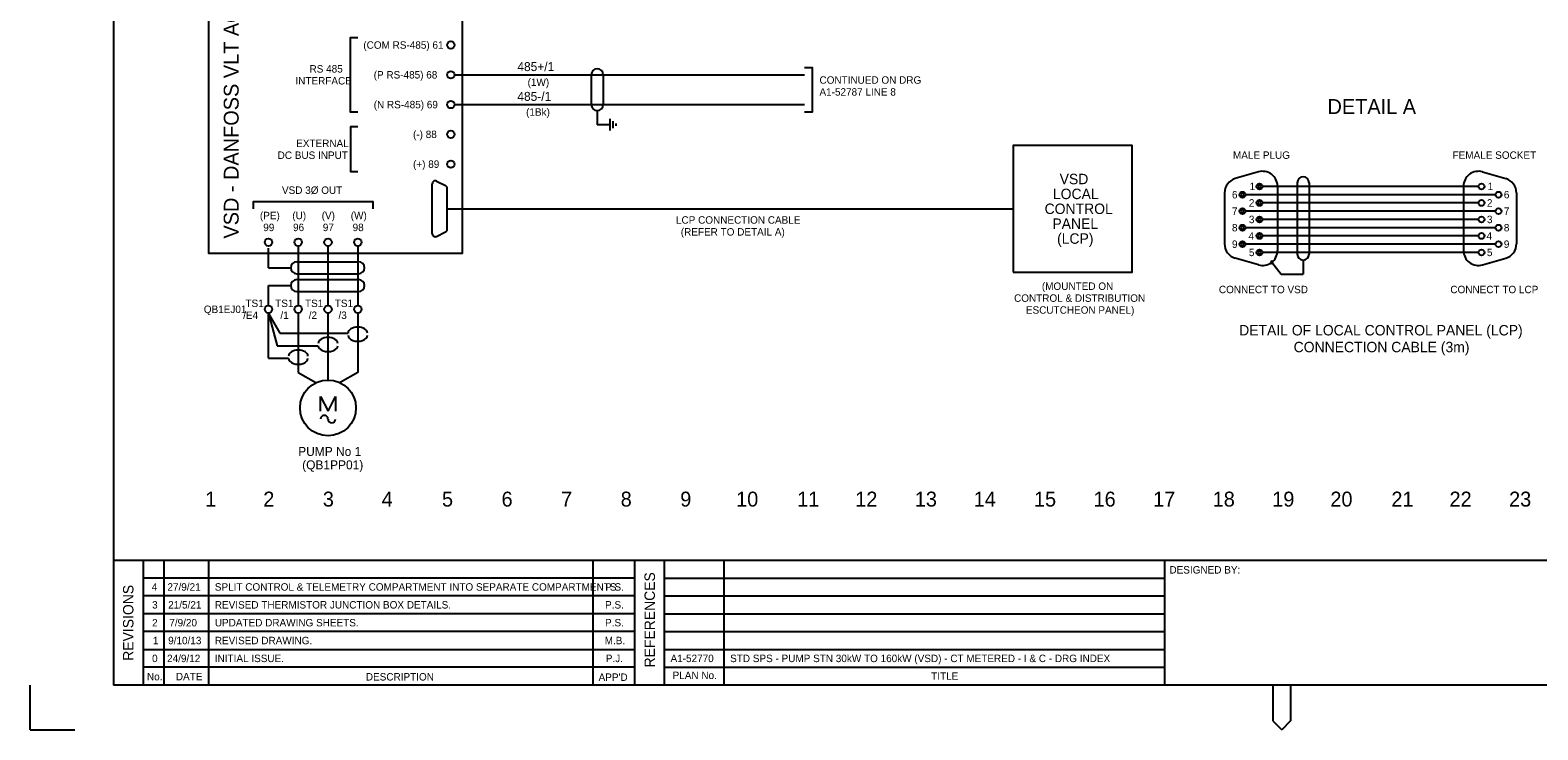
# Model space of a CAD drawing. Extents: x 0 to 841, y 0 to 594.
# Drawn here: x 0 to 506, y 0 to 235 of the extents above; entities that cross this region are included whole.
import ezdxf

# ---------------------------------------------------------------- set-up
doc = ezdxf.new("R2010")
doc.units = 0
for name, color, linetype in [('A1BORDER', 7, 'Continuous'), ('BASE', 7, 'Continuous'), ('Level 1', 7, 'Continuous'), ('Level 10', 7, 'Continuous'), ('Level 4', 7, 'Continuous'), ('Level 5', 7, 'Continuous'), ('Level 6', 7, 'Continuous'), ('Screen', 7, 'Continuous')]:
    doc.layers.add(name, color=color, linetype=linetype)

msp = doc.modelspace()

# ---------------------------------------------------------------- linework, layer by layer
at = {"layer": 'A1BORDER'}
for p, q in [((28, 581), (28, 15)), ((28, 57), (829, 57)), ((38, 15), (38, 57)), ((45, 15), (45, 57)), ((60, 15), (60, 57)), ((189, 15), (189, 57)), ((203, 15), (203, 57)), ((213, 15), (213, 57)), ((233, 15), (233, 57)), ((381, 15), (381, 57)), ((203, 51), (38, 51)), ((213, 51), (381, 51)), ((203, 45), (38, 45)), ((213, 45), (381, 45)), ((203, 39), (38, 39)), ((213, 39), (381, 39)), ((203, 33), (38, 33)), ((213, 33), (381, 33)), ((38, 27), (203, 27)), ((213, 27), (381, 27)), ((203, 21), (38, 21)), ((213, 21), (381, 21)), ((0, 0), (0, 15)), ((829, 15), (28, 15)), ((417.19, 15), (417.19, 3)), ((423.19, 15), (423.19, 3)), ((0, 0), (15, 0)), ((417.19, 3), (420.19, 0)), ((423.19, 3), (420.19, 0))]:
    msp.add_line(p, q, dxfattribs=at)
at = {"layer": 'BASE'}
for p, q in [((188.37, 220), (188.37, 210)), ((192.37, 220), (192.37, 210)), ((190.37, 208), (190.37, 203.25)), ((194.74, 203.25), (190.37, 203.25)), ((412.38, 187.39), (404.58, 185.12)), ((487.62, 187.39), (495.42, 185.12)), ((486.28, 182.5), (413.72, 182.5)), ((418.78, 182.59), (418.78, 160.97)), ((425.39, 183.76), (425.39, 159.8)), ((429.39, 183.76), (429.39, 159.8)), ((481.22, 182.59), (481.22, 160.97)), ((400.98, 180.32), (400.98, 163.24)), ((491.96, 179.73), (408.04, 179.73)), ((499.02, 180.32), (499.02, 163.24)), ((491.96, 174.19), (408.04, 174.19)), ((486.28, 176.96), (413.72, 176.96)), ((491.96, 168.65), (408.04, 168.65)), ((486.28, 171.42), (413.72, 171.42)), ((491.96, 163.11), (408.04, 163.11)), ((486.28, 165.88), (413.72, 165.88)), ((412.38, 156.17), (404.58, 158.44)), ((486.28, 160.34), (413.72, 160.34)), ((416.87, 157.04), (420.02, 153.05)), ((427.39, 157.8), (427.39, 153.05)), ((487.62, 156.17), (495.42, 158.44)), ((420.02, 153.05), (427.39, 153.05))]:
    msp.add_line(p, q, dxfattribs=at)
for centre in [(412.72, 182.5), (487.28, 182.5), (407.04, 179.73), (412.72, 176.96), (487.28, 176.96), (492.96, 179.73), (407.04, 174.19), (412.72, 171.42), (487.28, 171.42), (492.96, 174.19), (407.04, 168.65), (492.96, 168.65), (407.04, 163.11), (412.72, 165.88), (487.28, 165.88), (492.96, 163.11), (412.72, 160.34), (487.28, 160.34)]:
    msp.add_circle(centre, 1, dxfattribs=at)
for centre, radius, start, end in [((190.37, 220), 2, 0, 180), ((190.37, 210), 2, 180, 0), ((413.78, 182.59), 5, 0, 106.2177), ((486.22, 182.59), 5, 73.7823, 180), ((405.98, 180.32), 5, 106.2177, 180), ((412.72, 182.5), 0.5, 0, 180), ((412.72, 182.5), 0.5, 180, 0), ((427.39, 183.76), 2, 0, 180), ((494.02, 180.32), 5, 0, 73.7823), ((407.04, 179.73), 0.5, 0, 180), ((407.04, 179.73), 0.5, 180, 0), ((412.72, 176.96), 0.5, 0, 180), ((407.04, 174.19), 0.5, 0, 180), ((407.04, 174.19), 0.5, 180, 0), ((412.72, 176.96), 0.5, 180, 0), ((407.04, 168.65), 0.5, 0, 180), ((407.04, 168.65), 0.5, 180, 0), ((412.72, 171.42), 0.5, 0, 180), ((412.72, 171.42), 0.5, 180, 0), ((405.98, 163.24), 5, 180, 253.7823), ((407.04, 163.11), 0.5, 0, 180), ((407.04, 163.11), 0.5, 180, 0), ((412.72, 165.88), 0.5, 0, 180), ((412.72, 165.88), 0.5, 180, 0), ((494.02, 163.24), 5, 286.2177, 0), ((412.72, 160.34), 0.5, 0, 180), ((412.72, 160.34), 0.5, 180, 0), ((413.78, 160.97), 5, 253.7823, 0), ((416.87, 157.04), 0.375, 0, 180), ((416.87, 157.04), 0.375, 180, 0), ((427.39, 159.8), 2, 180, 0), ((486.22, 160.97), 5, 180, 286.2177)]:
    msp.add_arc(centre, radius, start, end, dxfattribs=at)
at = {"layer": 'Level 1'}
for p, q in [((135, 166.62), (135, 183.38)), ((136.45, 184.28), (139.45, 182.78)), ((140, 168.12), (140, 181.88)), ((140, 175), (330, 175)), ((136.45, 165.72), (139.45, 167.22)), ((90, 162.5), (90, 142.5)), ((100, 142.5), (100, 162.5)), ((110, 162.5), (110, 142.5)), ((90, 140), (90, 120)), ((100, 117.5), (100, 140)), ((110, 140), (110, 120))]:
    msp.add_line(p, q, dxfattribs=at)
for points in [[(60, 480), (145, 480), (145, 160), (60, 160)], [(330, 153.75), (370, 153.75), (370, 196.25), (330, 196.25)]]:
    msp.add_lwpolyline(points, close=True, dxfattribs=at)
for points in [[(110, 207.5), (107.5, 207.5), (107.5, 232.5), (110, 232.5)], [(260, 222.5), (262.5, 222.5), (262.5, 207.5), (260, 207.5)], [(110, 202.5), (107.5, 202.5), (107.5, 187.5), (110, 187.5)], [(75, 175), (75, 177.5), (115, 177.5), (115, 175)]]:
    msp.add_lwpolyline(points, dxfattribs=at)
for centre, start, end in [((136, 183.38), 63.4349, 180), ((139, 181.88), 0, 63.4349), ((139, 168.12), 296.5651, 360), ((136, 166.62), 180, 296.5651)]:
    msp.add_arc(centre, 1, start, end, dxfattribs=at)
at = {"layer": 'Level 10'}
for p, q in [((194.74, 201.25), (194.74, 205.25)), ((195.74, 202.05), (195.74, 204.45)), ((196.74, 202.85), (196.74, 203.65))]:
    msp.add_line(p, q, dxfattribs=at)
at = {"layer": 'Level 4'}
for p, q in [((97.49, 112), (100, 107)), ((97.49, 107), (97.49, 112)), ((100, 107), (102.51, 112)), ((102.51, 112), (102.51, 107))]:
    msp.add_line(p, q, dxfattribs=at)
for centre, radius in [((80, 163.75), 1.25), ((90, 163.75), 1.25), ((100, 163.75), 1.25), ((110, 163.75), 1.25), ((80, 141.25), 1.25), ((90, 141.25), 1.25), ((100, 141.25), 1.25), ((110, 141.25), 1.25), ((100, 108.12), 9.38)]:
    msp.add_circle(centre, radius, dxfattribs=at)
for centre, start, end in [((98.75, 104.38), 0, 180), ((101.25, 104.38), 180, 360)]:
    msp.add_arc(centre, 1.24, start, end, dxfattribs=at)
at = {"layer": 'Level 5'}
for p, q in [((90, 120), (95.89, 116.61)), ((110, 120), (104.11, 116.61))]:
    msp.add_line(p, q, dxfattribs=at)
for centre in [(141.25, 230), (141.25, 220), (141.25, 210), (141.25, 200), (141.25, 190)]:
    msp.add_circle(centre, 1.25, dxfattribs=at)
at = {"layer": 'Level 6'}
for p, q in [((142.5, 220), (260, 220)), ((142.5, 210), (260, 210))]:
    msp.add_line(p, q, dxfattribs=at)
at = {"layer": 'Screen'}
for p, q in [((80, 155.21), (80, 161.82)), ((89.52, 157.21), (110.27, 157.21)), ((80, 155.21), (87.52, 155.21)), ((89.52, 153.21), (110.27, 153.21)), ((80, 149.21), (87.52, 149.21)), ((80, 142.37), (80, 149.21)), ((89.52, 151.21), (110.27, 151.21)), ((89.52, 147.21), (110.27, 147.21)), ((80, 139.87), (82.9, 129.03)), ((80, 124.78), (80, 139.87)), ((80, 139.87), (83.8, 133.28)), ((83.8, 133.28), (106.75, 133.28)), ((82.9, 129.03), (96.75, 129.03)), ((80, 124.78), (86.75, 124.78))]:
    msp.add_line(p, q, dxfattribs=at)
for centre, start, end in [((89.52, 155.21), 90, 270), ((110.27, 155.21), 270, 90), ((89.52, 149.21), 90, 270), ((110.27, 149.21), 270, 90)]:
    msp.add_arc(centre, 2, start, end, dxfattribs=at)
for centre, start_param, end_param in [((100, 129.78), 3.141593, 6.283185), ((110, 133.28), 3.141593, 6.283185), ((110, 132.53), 0, 3.141593), ((90, 125.53), 3.141593, 6.283185), ((100, 129.03), 0, 3.141593), ((90, 124.78), 0, 3.141593)]:
    msp.add_ellipse(centre, major_axis=(-3.25, 0), ratio=0.615385, start_param=start_param, end_param=end_param, dxfattribs=at)

# ---------------------------------------------------------------- texts
at = {"layer": 'A1BORDER'}
for s, p in [('REFERENCES', (209.76, 20.96)), ('REVISIONS', (34.68, 23.2))]:
    msp.add_text(s, height=3.5, rotation=90, dxfattribs=at).set_placement(p)
for s, p in [('DESIGNED BY:', (382.5, 52.5)), ('No.', (39.21, 16.65)), ('DATE', (48.92, 16.65)), ('DESCRIPTION', (112.71, 16.57)), ("APP'D", (190.85, 16.44)), ('PLAN No.', (215.69, 17.06)), ('TITLE', (302.5, 16.81))]:
    msp.add_text(s, height=2.5, dxfattribs=at).set_placement(p)
at = {"layer": 'BASE'}
for s, height, p in [('DETAIL A', 5, (435.56, 206.84)), ('MALE PLUG', 2.5, (403.83, 191.78)), ('FEMALE SOCKET', 2.5, (477.56, 191.78)), ('1', 2.5, (409.42, 181.26)), ('1', 2.5, (489.34, 181.26)), ('6', 2.5, (403.49, 178.49)), ('2', 2.5, (409.17, 175.72)), ('2', 2.5, (489.09, 175.72)), ('6', 2.5, (494.77, 178.49)), ('7', 2.5, (403.49, 172.95)), ('3', 2.5, (409.17, 170.18)), ('3', 2.5, (489.09, 170.18)), ('7', 2.5, (494.77, 172.95)), ('8', 2.5, (403.49, 167.41)), ('4', 2.5, (409.05, 164.64)), ('4', 2.5, (488.96, 164.64)), ('8', 2.5, (494.77, 167.41)), ('9', 2.5, (403.49, 161.87)), ('9', 2.5, (494.77, 161.87)), ('5', 2.5, (409.17, 159.1)), ('5', 2.5, (489.09, 159.1)), ('CONNECT TO VSD', 2.5, (399.1, 146.65)), ('CONNECT TO LCP', 2.5, (476.81, 146.65)), ('DETAIL OF LOCAL CONTROL PANEL (LCP)', 3.5, (405.9, 132.47)), ('CONNECTION CABLE (3m)', 3.5, (424.2, 126.82))]:
    msp.add_text(s, height=height, dxfattribs=at).set_placement(p)
at = {"layer": 'Level 1'}
msp.add_text('VSD - DANFOSS VLT AQUA FC 202', height=5, rotation=90, dxfattribs=at).set_placement((70, 165))
for s, height, p in [('(COM RS-485) 61', 2.5, (111.85, 228.75)), ('RS 485', 2.5, (93.79, 220.75)), ('INTERFACE', 2.5, (89.06, 216.75)), ('(P RS-485) 68', 2.5, (115.34, 218.75)), ('CONTINUED ON DRG', 2.5, (265, 217)), ('A1-52787 LINE 8', 2.5, (265, 213)), ('(N RS-485) 69', 2.5, (115.34, 208.75)), ('EXTERNAL', 2.5, (89.31, 195.75)), ('(-) 88', 2.5, (128.54, 198.75)), ('DC BUS INPUT', 2.5, (83.09, 191.75)), ('(+) 89', 2.5, (128.54, 188.75)), ('VSD 3Ø OUT', 2.5, (84.54, 180)), ('VSD', 3.5, (345.64, 183.25)), ('LOCAL', 3.5, (343.38, 178.25)), ('(PE)', 2.5, (77.14, 171.5)), ('(U)', 2.5, (88.01, 171.5)), ('(V)', 2.5, (97.88, 171.5)), ('(W)', 2.5, (107.64, 171.5)), ('LCP CONNECTION CABLE', 2.5, (216.82, 170)), ('CONTROL', 3.5, (340.59, 173.25)), ('99', 2.5, (78.26, 167.5)), ('96', 2.5, (88.26, 167.5)), ('97', 2.5, (98.26, 167.5)), ('98', 2.5, (108.26, 167.5)), ('(REFER TO DETAIL A)', 2.5, (218.44, 166)), ('PANEL', 3.5, (343.2, 168.25)), ('(LCP)', 3.5, (344.77, 163.25)), ('(MOUNTED ON', 2.5, (339.67, 147.76)), ('CONTROL & DISTRIBUTION', 2.5, (330.33, 143.76)), ('ESCUTCHEON PANEL)', 2.5, (334.31, 139.76)), ('PUMP No 1', 3, (89.99, 92)), ('(QB1PP01)', 3, (91.33, 87.5)), ('1', 5, (58.76, 75)), ('2', 5, (78.26, 75)), ('3', 5, (98.26, 75)), ('4', 5, (118.01, 75)), ('5', 5, (138.26, 75)), ('6', 5, (158.26, 75)), ('7', 5, (178.26, 75)), ('8', 5, (198.26, 75)), ('9', 5, (218.26, 75)), ('10', 5, (237.01, 75)), ('11', 5, (257.51, 75)), ('12', 5, (277.01, 75)), ('13', 5, (297.01, 75)), ('14', 5, (316.77, 75)), ('15', 5, (337.01, 75)), ('16', 5, (357.01, 75)), ('17', 5, (377.01, 75)), ('18', 5, (397.01, 75)), ('19', 5, (417.01, 75)), ('20', 5, (436.52, 75)), ('21', 5, (457.01, 75)), ('22', 5, (476.52, 75)), ('23', 5, (496.52, 75)), ('4', 2.5, (40.82, 46.75)), ('27/9/21', 2.5, (46.09, 46.75)), ('SPLIT CONTROL & TELEMETRY COMPARTMENT INTO SEPARATE COMPARTMENTS.', 2.5, (62, 46.75)), ('P.S.', 2.5, (193.02, 46.75)), ('3', 2.5, (40.94, 40.75)), ('21/5/21', 2.5, (46.34, 40.75)), ('REVISED THERMISTOR JUNCTION BOX DETAILS.', 2.5, (62, 40.75)), ('P.S.', 2.5, (193.02, 40.75)), ('2', 2.5, (40.94, 34.75)), ('7/9/20', 2.5, (46.72, 34.75)), ('UPDATED DRAWING SHEETS.', 2.5, (62, 34.75)), ('P.S.', 2.5, (193.02, 34.75)), ('1', 2.5, (41.19, 28.75)), ('9/10/13', 2.5, (46.34, 28.75)), ('REVISED DRAWING.', 2.5, (62, 28.75)), ('M.B.', 2.5, (192.89, 28.75)), ('24/9/12', 2.5, (45.97, 22.75)), ('STD SPS - PUMP STN 30kW TO 160kW (VSD) - CT METERED - I & C - DRG INDEX', 2.5, (235, 22.75)), ('0', 2.5, (40.94, 22.75)), ('INITIAL ISSUE.', 2.5, (62, 22.75)), ('P.J.', 2.5, (193.26, 22.75)), ('A1-52770', 2.5, (215, 22.75))]:
    msp.add_text(s, height=height, dxfattribs=at).set_placement(p)
at = {"layer": 'Level 5'}
for s, height, p in [('485+/1', 3, (163.57, 221.25)), ('(1W)', 2.5, (167.01, 216.25)), ('485-/1', 3, (163.57, 211.25)), ('(1Bk)', 2.5, (166.51, 206.25))]:
    msp.add_text(s, height=height, dxfattribs=at).set_placement(p)
at = {"layer": 'Level 6'}
for s, p in [('QB1EJ01', (58.3, 140)), ('TS1', (72.27, 142)), ('TS1', (82.27, 142)), ('TS1', (92.27, 142)), ('TS1', (102.27, 142)), ('/E4', (71.52, 138)), ('/1', (84.01, 138)), ('/2', (93.52, 138)), ('/3', (103.52, 138))]:
    msp.add_text(s, height=2.5, dxfattribs=at).set_placement(p)

doc.saveas('drawing.dxf')
